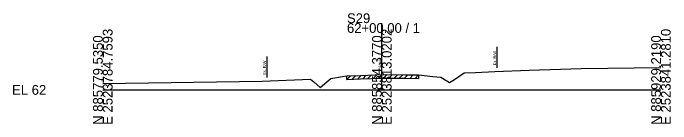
# Model space of a CAD drawing. Extents: x -26 to 163, y -10 to 4024.
# Drawn here: x -25.7 to 162.8, y 1990.3 to 2021.9 of the extents above; entities that cross this region are included whole.
import ezdxf

# ---------------------------------------------------------------- set-up
doc = ezdxf.new("R2010")
doc.units = 0
for name, color, linetype in [('RD_GPK_XS_Cell', 7, 'Continuous'), ('RD_XS_ExGround', 7, 'Continuous'), ('RD_XS_ExPaveRet', 7, 'Continuous'), ('RD_XS_ExRW', 7, 'Continuous'), ('RD_XS_TX_Elev_EX', 7, 'Continuous')]:
    doc.layers.add(name, color=color, linetype=linetype)

msp = doc.modelspace()

# ---------------------------------------------------------------- linework, layer by layer
at = {"layer": 'RD_GPK_XS_Cell'}
for p, q in [((80, 2000), (80, 2019.1)), ((0, 2000), (80, 2000)), ((80, 2000), (160, 2000))]:
    msp.add_line(p, q, dxfattribs=at)
at = {"layer": 'RD_XS_ExGround'}
for p, q in [((122.25, 2005.64), (137.16, 2006.17)), ((137.16, 2006.17), (160, 2006.37)), ((70, 2003.99), (73.89, 2004.16)), ((73.89, 2004.16), (80.06, 2004.4)), ((80.06, 2004.4), (86.82, 2004.32)), ((86.82, 2004.32), (90.49, 2004.27)), ((90.49, 2004.27), (94.65, 2003.85)), ((100.79, 2003.02), (103.56, 2004.93)), ((103.56, 2004.93), (106.83, 2005.02)), ((106.83, 2005.02), (112.41, 2005.27)), ((112.41, 2005.27), (122.25, 2005.64)), ((0, 2001.87), (45.7, 2002.48)), ((45.7, 2002.48), (59.54, 2003.04)), ((59.54, 2003.04), (60.51, 2002.28)), ((60.51, 2002.28), (62.33, 2000.71)), ((62.33, 2000.71), (64.22, 2002.33)), ((64.22, 2002.33), (65.39, 2003.27)), ((65.39, 2003.27), (68.75, 2003.85)), ((68.75, 2003.85), (70, 2003.99)), ((94.65, 2003.85), (96.93, 2003.67)), ((96.93, 2003.67), (98.63, 2002.6)), ((98.63, 2002.6), (99.38, 2002.1)), ((99.38, 2002.1), (100.79, 2003.02))]:
    msp.add_line(p, q, dxfattribs=at)
at = {"layer": 'RD_XS_ExPaveRet'}
for p, q in [((73, 2003.12), (74.04, 2004.16)), ((74.5, 2003.18), (75.54, 2004.22)), ((76, 2003.24), (77.04, 2004.28)), ((77.5, 2003.3), (78.54, 2004.34)), ((79, 2003.36), (80.04, 2004.4)), ((80.5, 2003.39), (81.49, 2004.38)), ((82, 2003.38), (82.99, 2004.36)), ((83.5, 2003.36), (84.49, 2004.35)), ((85, 2003.34), (85.99, 2004.33)), ((86.5, 2003.32), (87.49, 2004.31)), ((88, 2003.3), (88.99, 2004.29)), ((89.5, 2003.29), (90.49, 2004.27)), ((90.49, 2004.27), (90.49, 2003.27)), ((70, 2002.99), (71.04, 2004.04)), ((70, 2002.99), (70, 2003.99)), ((70, 2002.99), (73.89, 2003.16)), ((71.5, 2003.05), (72.54, 2004.1)), ((73.89, 2003.16), (80.06, 2003.4)), ((80.06, 2003.4), (86.82, 2003.32)), ((86.82, 2003.32), (90.49, 2003.27))]:
    msp.add_line(p, q, dxfattribs=at)
at = {"layer": 'RD_XS_ExRW'}
for p, q in [((113, 2012.29), (113, 2006.29)), ((47, 2009.53), (47, 2003.53))]:
    msp.add_line(p, q, dxfattribs=at)

# ---------------------------------------------------------------- texts
at = {"layer": 'RD_GPK_XS_Cell'}
for s, p in [('S29', (70, 2019.1)), ('62+00.00 / 1', (70, 2016.3)), ('EL 62', (-26, 1998.6))]:
    msp.add_text(s, height=2.8, dxfattribs=at).set_placement(p)
for s, p in [('E 2523784.7593', (2.8, 1990)), ('E 2523841.2810', (162.8, 1990)), ('N 885779.5350', (0, 1990)), ('N 885854.3770', (80, 1990)), ('E 2523813.0202', (82.8, 1990)), ('N 885929.2190', (160, 1990))]:
    msp.add_text(s, height=2.8, rotation=90, dxfattribs=at).set_placement(p)
at = {"layer": 'RD_XS_ExRW'}
for p in [(112.75, 2007.08), (46.75, 2004.32)]:
    msp.add_text('Ex. R/W ', height=0.8, rotation=90, dxfattribs=at).set_placement(p)
at = {"layer": 'RD_XS_TX_Elev_EX'}
msp.add_text('66.40', height=0.8, rotation=90, dxfattribs=at).set_placement((79.9, 2006.4))

doc.saveas('drawing.dxf')
